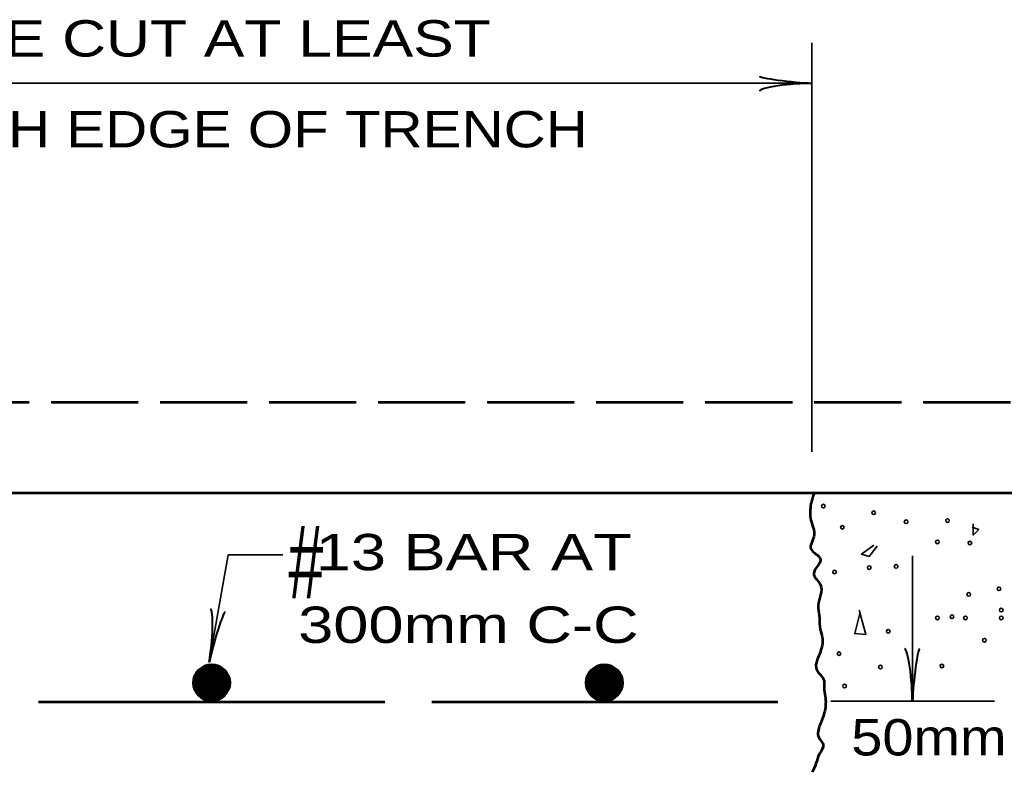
# Model space of a CAD drawing. Extents: x -617 to 238, y 23 to 567.
# Drawn here: x -228.6 to -163.5, y 382.7 to 432.4 of the extents above; entities that cross this region are included whole.
import ezdxf
from ezdxf.enums import TextEntityAlignment as Align

# ---------------------------------------------------------------- set-up
doc = ezdxf.new("R2010")
doc.units = 0
doc.header["$LTSCALE"] = 0.96
doc.linetypes.add('LONG_DASHED', pattern=[7.5, 6, -1.5])
doc.layers.add('1', color=7, linetype='Continuous', lineweight=40)

msp = doc.modelspace()

# ---------------------------------------------------------------- linework, layer by layer
at = {"layer": '1', "lineweight": 35}
for p, q in [((-176.2353, 403.8593), (-176.2353, 430.8593)), ((-283.0353, 428.2004), (-176.2353, 428.2004)), ((-216.0409, 389.9636), (-214.7907, 397.0543)), ((-214.7907, 397.0543), (-211.1906, 397.0543)), ((-169.5989, 387.3748), (-169.5989, 396.9748)), ((-174.9802, 387.3748), (-164.1802, 387.3748))]:
    msp.add_line(p, q, dxfattribs=at)
at = {"layer": '1', "linetype": 'LONG_DASHED', "lineweight": 53}
msp.add_line((-327.291, 407.1379), (-135.291, 407.1379), dxfattribs=at)
at = {"layer": '1', "lineweight": 53}
for p, q in [((-327.291, 401.1379), (-135.291, 401.1379)), ((-227.3125, 387.3379), (-204.45, 387.3379)), ((-201.3475, 387.3379), (-178.491, 387.3379))]:
    msp.add_line(p, q, dxfattribs=at)
at = {"layer": '1', "lineweight": 35}
for points in [[(-165.5847, 399.0837), (-165.5847, 398.345), (-165.2154, 398.7143), (-165.6586, 398.8621)], [(-172.1592, 397.6802), (-172.9718, 397.0892), (-172.4547, 396.9415), (-171.9376, 397.6063)], [(-173.0456, 393.2479), (-173.415, 391.8444), (-172.6763, 391.7705), (-173.1195, 393.3957)]]:
    msp.add_lwpolyline(points, dxfattribs=at)
for centre in [(-175.4834, 400.2656), (-172.1592, 399.8224), (-170.017, 399.2314), (-167.2838, 399.3053), (-174.2276, 398.8621), (-167.9486, 397.9018), (-165.8064, 397.8279), (-174.7447, 395.9073), (-172.4547, 396.2028), (-170.6818, 396.2766), (-163.8857, 394.7992), (-165.8802, 394.4299), (-163.738, 393.3957), (-167.9486, 392.8786), (-166.9883, 392.9525), (-166.1018, 392.8786), (-163.738, 392.8786), (-171.1989, 391.9921), (-164.846, 391.4012), (-174.4492, 390.5147), (-171.716, 389.6283), (-167.6531, 389.7022), (-174.0798, 388.3725)]:
    msp.add_circle(centre, 0.12, dxfattribs=at)
at = {"layer": '1', "lineweight": 53}
for centre, radius in [((-215.8876, 388.5949), 1.2), ((-215.8925, 388.5726), 1.0988), ((-215.895, 388.6419), 1.032), ((-215.8925, 388.6122), 0.9607), ((-189.9492, 388.595), 1.2), ((-189.9541, 388.5727), 1.0988), ((-189.9566, 388.642), 1.032), ((-189.9541, 388.6123), 0.9607), ((-215.8802, 388.5801), 0.884), ((-215.8679, 388.5677), 0.8128), ((-215.8555, 388.5702), 0.7422), ((-215.8481, 388.5801), 0.6733), ((-215.8406, 388.6073), 0.6068), ((-215.8407, 388.6098), 0.5282), ((-215.8283, 388.6147), 0.4508), ((-215.8308, 388.6147), 0.3792), ((-215.8357, 388.6345), 0.3052), ((-189.9418, 388.5802), 0.884), ((-189.9295, 388.5678), 0.8128), ((-189.9171, 388.5703), 0.7422), ((-189.9096, 388.5802), 0.6733), ((-189.9022, 388.6073), 0.6068), ((-189.9023, 388.6098), 0.5282), ((-189.8899, 388.6148), 0.4508), ((-189.8924, 388.6148), 0.3792), ((-189.8973, 388.6346), 0.3052), ((-215.8332, 388.627), 0.2278), ((-215.8307, 388.6345), 0.166), ((-215.8208, 388.6245), 0.1015), ((-215.8209, 388.627), 0.0427), ((-189.8948, 388.6272), 0.2278), ((-189.8923, 388.6346), 0.166), ((-189.8824, 388.6247), 0.1015), ((-189.8825, 388.6272), 0.0427)]:
    msp.add_circle(centre, radius, dxfattribs=at)
at = {"layer": '1'}
for centre, major_axis, ratio, start_param, end_param in [((-177.5799, 428.4543), (2.1077, -0.2108), 0.07063, 3.1407148, 5.41811), ((-177.5447, 427.8688), (2.1428, 0.1874), 0.122415, 0.8963533, 3.1415927), ((-216.14, 391.3107), (-0.1876, -2.1428), 0.122415, 0.8963533, 3.1415927), ((-215.5573, 391.2437), (0.5736, 2.0391), 0.07063, 6.2823074, 8.5597026), ((-169.9305, 388.6842), (0.1874, -2.1428), 0.122415, 0.8963533, 3.1415927), ((-169.345, 388.7194), (0.2108, 2.1077), 0.07063, 6.2823074, 8.5597026)]:
    msp.add_ellipse(centre, major_axis=major_axis, ratio=ratio, start_param=start_param, end_param=end_param, dxfattribs=at)
at = {"layer": '1', "lineweight": 53}
msp.add_spline([(-176.091, 401.1379), (-176.3427, 400.1661), (-176.2319, 399.0581), (-176.0842, 398.3563), (-176.3058, 397.433), (-175.6779, 396.7681), (-176.1211, 395.8078), (-175.6779, 395.0691), (-175.8256, 393.7025), (-175.7518, 393.0377), (-175.7148, 392.299), (-175.5671, 391.6342), (-175.5671, 391.0432), (-175.8995, 389.3812), (-175.4932, 388.8641), (-175.4194, 388.1254), (-175.3455, 387.5714), (-175.4194, 386.611), (-175.7148, 385.7985), (-175.7887, 384.9859), (-175.4932, 384.5058), (-175.7518, 383.8779), (-175.9734, 383.25), (-176.2318, 382.6771)], degree=3, dxfattribs=at)

# ---------------------------------------------------------------- texts
at = {"layer": '1'}
for s, height, width, p in [('PAVEMENT TO BE CUT AT LEAST', 2.4, 1.25, (-229.7671, 429.9619)), ('300mm BEYOND EACH EDGE OF TRENCH', 2.4, 1.2, (-229.767, 423.9619)), ('#', 4.8, 0.65, (-209.6569, 394.1751)), ('50mm', 2.4, 1.15, (-168.5117, 383.7905))]:
    msp.add_text(s, height=height, dxfattribs=dict(at, width=width)).set_placement(p, align=Align.CENTER)
at = {"layer": '1', "width": 1.3}
for s, p in [(' 13 BAR AT', (-210.1686, 396.0265)), ('300mm C-C', (-210.1686, 391.2265))]:
    msp.add_text(s, height=2.4, dxfattribs=at).set_placement(p)

doc.saveas('drawing.dxf')
